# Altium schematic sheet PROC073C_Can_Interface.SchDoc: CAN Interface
size 431 x 279 mm; Date: Not shown in title block; ApprovedBy: Not shown in title block; CheckedBy: Not shown in title block; Author: Not shown in title block; CompanyName: Not shown in title block; DrawnBy: Charles F. Oladimeji; Engineer: Not shown in title block; Organization: Not shown in title block; Address1: Not shown in title block; Address2: Not shown in title block; Address3: Not shown in title block; Address4: Not shown in title block; DocumentNumber: 12; Revision: Use project parameter SCH_Rev; SheetNumber: 12; SheetTotal: 13; PageSetup: Record=PageOptions¦CenterHorizontal=True¦CenterVertical=True¦PrintScale=1.00¦XCorrection=1.00¦YCorrection=1.00¦PrintKind=0¦BorderSize=5000000¦LeftOffset=0¦BottomOffset=0¦Orientation=2¦PaperLength=1000¦PaperWidth=1000¦Scale=100¦PaperSource=15¦PrintQuality=600¦MediaType=1¦DitherType=10¦PaperKind=Letter¦PrintScaleMode=1
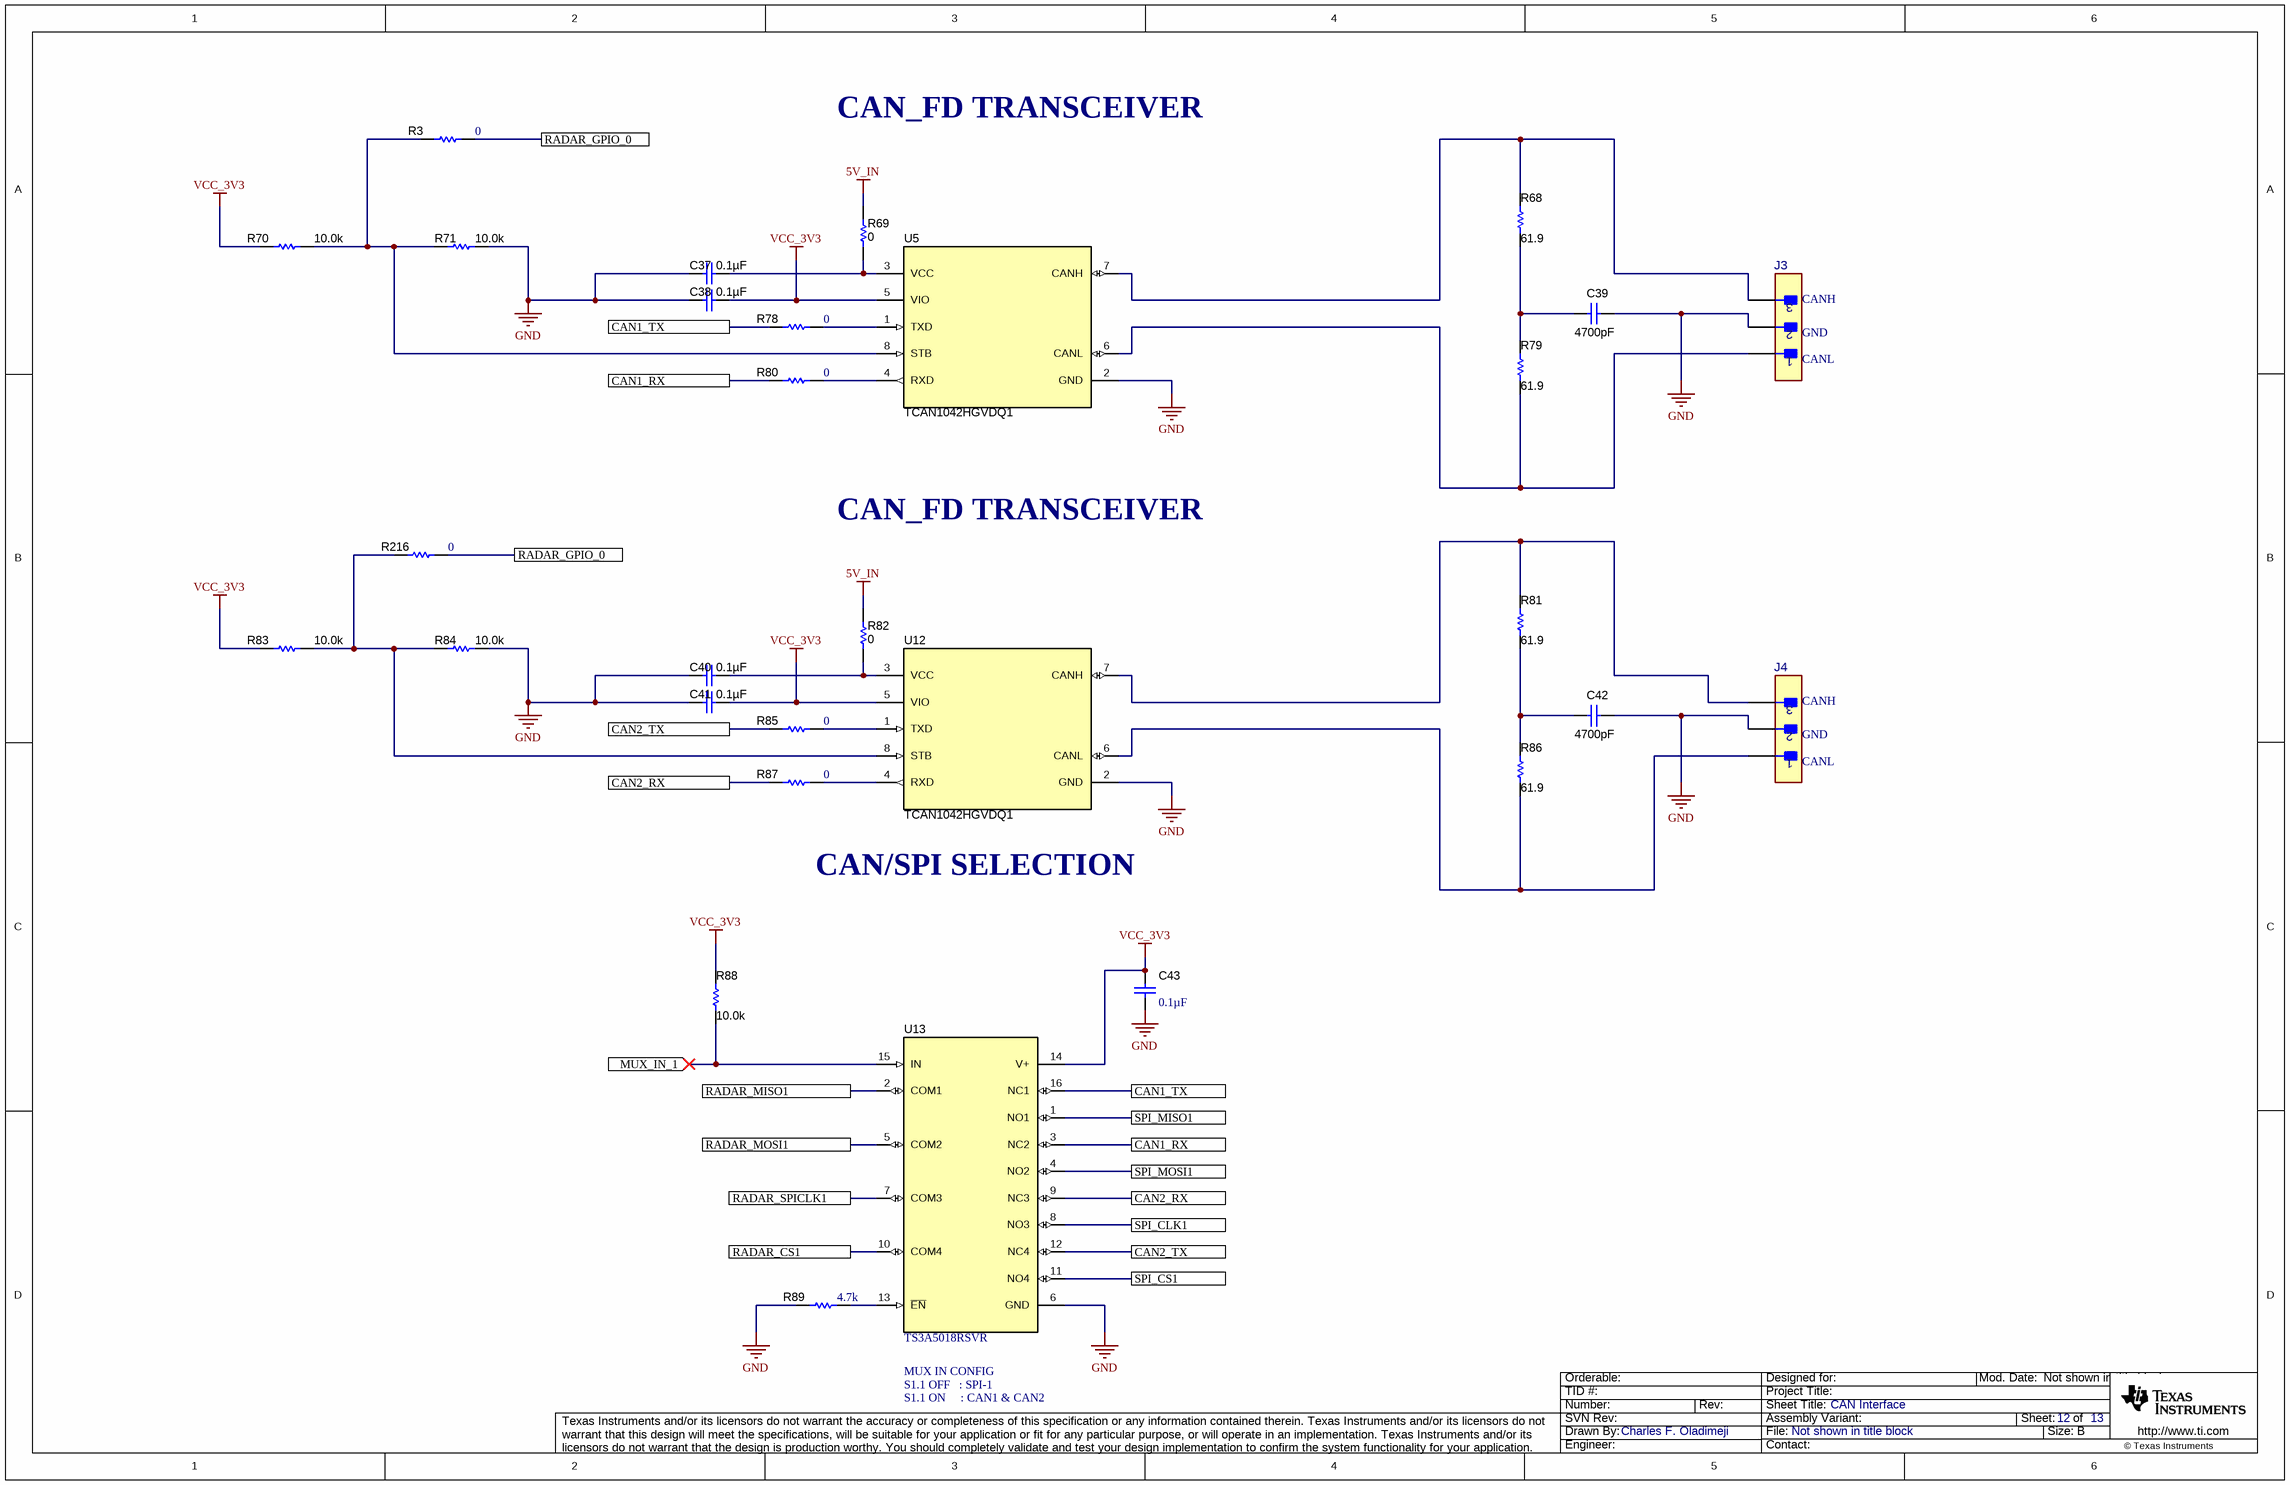
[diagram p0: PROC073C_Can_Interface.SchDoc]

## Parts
C37  ValueDisplayed: 0.1µF  [0402L]  (hidden comment: C0402C104K8RACTU)
C38  ValueDisplayed: 0.1µF  [0402L]  (hidden comment: C0402C104K8RACTU)
C39  ValueDisplayed: 4700pF  [0402L]  (hidden comment: GCM155R71H472KA37D)
C40  ValueDisplayed: 0.1µF  [0402L]  (hidden comment: C0402C104K8RACTU)
C41  ValueDisplayed: 0.1µF  [0402L]  (hidden comment: C0402C104K8RACTU)
C42  ValueDisplayed: 4700pF  [0402L]  (hidden comment: GCM155R71H472KA37D)
C43  ValueDisplayed: 0.1µF  [0402]  (hidden comment: C0402C104K8RACTU)
J3  M50-3930342  [FP-M50-3930342_HDR3-MFG]  (value not drawn)
J4  M50-3930342  [FP-M50-3930342_HDR3-MFG]  (value not drawn)
R3  ValueDisplayed: 0  [0402]  (hidden comment: ERJ-2GE0R00X)
R68  ValueDisplayed: 61.9  [0402L]  (hidden comment: CRCW040261R9FKED)
R69  ValueDisplayed: 0  [0201_Silk]  (hidden comment: CRCW02010000Z0ED)
R70  ValueDisplayed: 10.0k  [0402L]  (hidden comment: CRCW040210K0FKED)
R71  ValueDisplayed: 10.0k  [0402L]  (hidden comment: CRCW040210K0FKED)
R78  ValueDisplayed: 0  [0402]  (hidden comment: ERJ-2GE0R00X)
R79  ValueDisplayed: 61.9  [0402L]  (hidden comment: CRCW040261R9FKED)
R80  ValueDisplayed: 0  [0402]  (hidden comment: ERJ-2GE0R00X)
R81  ValueDisplayed: 61.9  [0402L]  (hidden comment: CRCW040261R9FKED)
R82  ValueDisplayed: 0  [0201_Silk]  (hidden comment: CRCW02010000Z0ED)
R83  ValueDisplayed: 10.0k  [0402L]  (hidden comment: CRCW040210K0FKED)
R84  ValueDisplayed: 10.0k  [0402L]  (hidden comment: CRCW040210K0FKED)
R85  ValueDisplayed: 0  [0402]  (hidden comment: ERJ-2GE0R00X)
R86  ValueDisplayed: 61.9  [0402L]  (hidden comment: CRCW040261R9FKED)
R87  ValueDisplayed: 0  [0402]  (hidden comment: ERJ-2GE0R00X)
R88  ValueDisplayed: 10.0k  [0402L]  (hidden comment: CRCW040210K0FKED)
R89  ValueDisplayed: 4.7k  [0402]  (hidden comment: CRCW04024K70JNED)
R216  ValueDisplayed: 0  [0402]  (hidden comment: ERJ-2GE0R00X)
U5  TCAN1042HGVDQ1  [D0008A_L]
U12  TCAN1042HGVDQ1  [D0008A_L]
U13  TS3A5018RSVR  [RSV0016A]

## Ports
CAN1_RX, CAN1_TX, CAN2_RX, CAN2_TX, MUX_IN_1 (in), RADAR_CS1, RADAR_GPIO_0, RADAR_MISO1, RADAR_MOSI1, RADAR_SPICLK1, SPI_CLK1, SPI_CS1, SPI_MISO1, SPI_MOSI1

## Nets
5V_IN: R69.2 R82.2
GND: C37.1 C38.1 C39.1 C40.1 C41.1 C42.1 C43.2 J3.2 J4.2 R71.2 R84.2 R89.1 U5.2(GND) U12.2(GND) U13.6(GND)
VCC_3V3: C38.2 C41.2 C43.1 R70.1 R83.1 R88.2 U5.5(VIO) U12.5(VIO) U13.14(V+)
CAN1_RX: R80.1 U13.3(NC2) ; port CAN1_RX
CAN1_TX: R78.1 U13.16(NC1) ; port CAN1_TX
CAN2_RX: R87.1 U13.9(NC3) ; port CAN2_RX
CAN2_TX: R85.1 U13.12(NC4) ; port CAN2_TX
MUX_IN_1: R88.1 U13.15(IN) ; port MUX_IN_1
RADAR_CS1: U13.10(COM4) ; port RADAR_CS1
RADAR_GPIO_0: R3.2 R216.2 ; port RADAR_GPIO_0
RADAR_MISO1: U13.2(COM1) ; port RADAR_MISO1
RADAR_MOSI1: U13.5(COM2) ; port RADAR_MOSI1
RADAR_SPICLK1: U13.7(COM3) ; port RADAR_SPICLK1
SPI_CLK1: U13.8(NO3) ; port SPI_CLK1
SPI_CS1: U13.11(NO4) ; port SPI_CS1
SPI_MISO1: U13.1(NO1) ; port SPI_MISO1
SPI_MOSI1: U13.4(NO2) ; port SPI_MOSI1
NetC37_2: C37.2 R69.1 U5.3(VCC)
NetC39_2: C39.2 R68.1 R79.2
NetC40_2: C40.2 R82.1 U12.3(VCC)
NetC42_2: C42.2 R81.1 R86.2
NetJ3_1: J3.1 R79.1 U5.6(CANL)
NetJ3_3: J3.3 R68.2 U5.7(CANH)
NetJ4_1: J4.1 R86.1 U12.6(CANL)
NetJ4_3: J4.3 R81.2 U12.7(CANH)
NetR3_1: R3.1 R70.2 R71.1 U5.8(STB)
NetR78_2: R78.2 U5.1(TXD)
NetR80_2: R80.2 U5.4(RXD)
NetR83_2: R83.2 R84.1 R216.1 U12.8(STB)
NetR85_2: R85.2 U12.1(TXD)
NetR87_2: R87.2 U12.4(RXD)
NetR89_2: R89.2 U13.13(~{EN})

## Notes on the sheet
- CAN_FD TRANSCEIVER
- (near J3) CANH
- (near J3) GND
- (near J3) CANL
- (near J4) CANH
- (near J4) GND
- (near J4) CANL
- CAN/SPI SELECTION
- MUX IN CONFIG
- S1.1 OFF   : SPI-1
- S1.1 ON     : CAN1 & CAN2

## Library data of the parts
C37 C38 C40 C41 = CMP-0078241-1: CAP, CERM, 0.1 µF, 10 V,+/- 10%, X7R, 0402; Manufacturer: Kemet; TaMin_C: -55°C; Polarized: N; SizeAreaWB_mm2: 3; U/M: EA; Value: 0.1uF; TaMax_C: 125°C; SizeZ_mm: 0.6; SizeX_mm: 1; SizeY_mm: 0.5; Cap_Case: 0402; Value2: 10V; CompType: Capacitor; Cap_F: 100nF; AEC Category: Q200
C39 C42 = CMP-0006361-2: CAP, CERM, 4700 pF, 50 V, +/- 10%, X7R, AEC-Q200 Grade 1, 0402; Manufacturer: MuRata; TaMin_C: -55°C; Polarized: N; SizeAreaWB_mm2: 3; Value1: Unknown; U/M: EA; Value: 4700pF; TaMax_C: 125°C; SizeZ_mm: 0.6; SizeX_mm: 1; SizeY_mm: 0.5; Cap_Case: 0402; Value2: 50V; AEC Qualified: Y; Cap_F: 4.7nF; AEC Category: Q200
C43 = CMP-0078241-1: CAP, CERM, 0.1 µF, 10 V,+/- 10%, X7R, 0402; Manufacturer: Kemet; TaMin_C: -55°C; Polarized: N; SizeAreaWB_mm2: 3; U/M: EA; Value: 0.1uF; TaMax_C: 125°C; SizeZ_mm: 0.6; SizeX_mm: 1; SizeY_mm: 0.5; Value2: 10V; CompType: Capacitor; Cap_F: 100nF; AEC Category: Q200
J3 J4 = CMP-0087785-1: CONN HEADER R/A 3POS 1.27MM; Manufacturer: Harwin; Row_Count: 1; Current_A: 1A; ContactFinish: Gold,Nickel
R3 R78 R80 R85 R87 R216 = CMP-0026992-3: RES, 0, 5%, 0.1 W, AEC-Q200 Grade 0, 0402; Manufacturer: Panasonic; Power_W: 100mW; TempCo: 600 ppm/C; Value_Code: 0000; Value: 0; EIA_Code: E24; SizeX_mm: 1; SizeY_mm: 0.5; SizeZ_mm: 0.6; Value2: 0.1W; CompType: Resistor; AEC Qualified: Y; VDC_V: 50V; AEC Category: Q200; SizeAreaWB_mm2: 3; INSTALLATION: DNP
R68 R79 R81 R86 = CMP-0026491-2: RES, 61.9, 1%, 0.063 W, AEC-Q200 Grade 0, 0402; Manufacturer: Vishay-Dale; Power_W: 63mW; TempCo: 100 ppm/C; Value_Code: 61R9; Value: 61.9; EIA_Code: E96; SizeX_mm: 1; SizeY_mm: 0.5; SizeZ_mm: 0.6; Value2: 0.063W; AEC Qualified: Y; VDC_V: 50V; AEC Category: Q200; AEC Grade: 0
R69 R82 = CMP-0027008-4: RES, 0, 5%, 0.05 W, 0201; Manufacturer: Vishay-Dale; Power_W: 50mW; TempCo: ppm/C; Value_Code: 0000; Value: 0; EIA_Code: E24; SizeX_mm: 0.6; SizeY_mm: 0.3; SizeZ_mm: 0.26; Value2: 0.05W; SizeArea_mm2: 0.18; AEC Qualified: N; AEC Category: Q200
R70 R71 R83 R84 R88 = CMP-0025958-3: RES, 10.0 k, 1%, 0.063 W, AEC-Q200 Grade 0, 0402; Manufacturer: Vishay-Dale; Power_W: 63mW; TempCo: 100 ppm/C; Value_Code: 10k0; Value: 10.0k; EIA_Code: E96; Res_ohm: 10k; SizeX_mm: 1; SizeY_mm: 0.5; SizeZ_mm: 0.6; Value2: 0.063W; AEC Qualified: Y; VDC_V: 50V; AEC Category: Q200; AEC Grade: 0
R89 = CMP-0026938-5: RES, 4.7 k, 5%, 0.063 W, AEC-Q200 Grade 0, 0402; Manufacturer: Vishay-Dale; Power_W: 63mW; TempCo: 200 ppm/C; Value_Code: 4k70; Value: 4.7k; EIA_Code: E24; SizeX_mm: 1; SizeY_mm: 0.5; SizeZ_mm: 0.6; Value2: 0.063W; AEC Qualified: Y; VDC_V: 50V; AEC Category: Q200; AEC Grade: 0
U5 U12 = CMP-0075992-1: Automotive Fault Protected CAN Transceiver With Flexible Data-Rate, D0008A (SOIC-8); Manufacturer: Texas Instruments; Alternate PartNumber: TCAN1042HGVDRQ1; SizeAreaWB_mm2: 56.58; SizeArea_mm2: 30.38; SizeZ_mm: 1.75; SizeY_mm: 6.2; U/M: EA; CompType: IC; SizeX_mm: 4.9
U13 = CMP-0067415-1: 10-Ohm Quad SPDT Analog Switch, RSV0016A (UQFN-16); Alternate Manufacturer: Texas Instruments; SizeAreaWB_mm2: 10.08; U/M: EA; SizeZ_mm: 0.55; SizeX_mm: 1.8; SizeY_mm: 2.6; SizeArea_mm2: 4.68; CompType: IC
